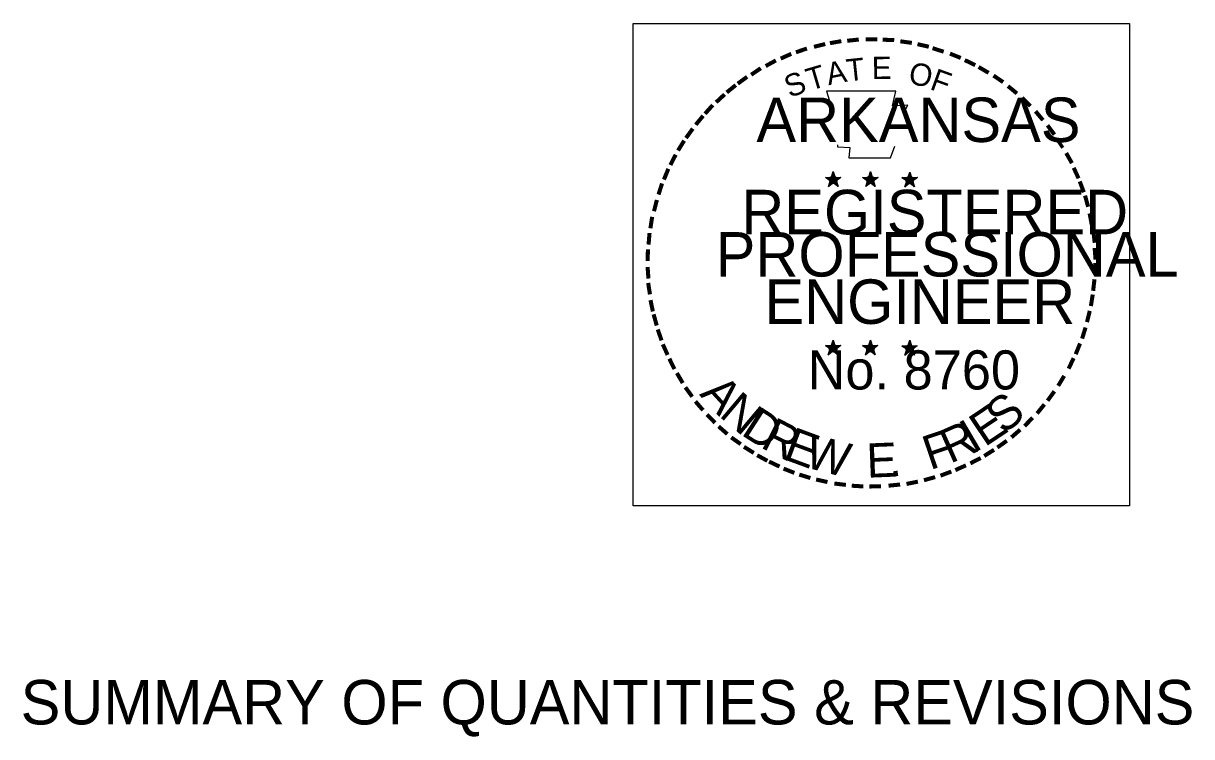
# Model space of a CAD drawing. Extents: x 1226912 to 1228117, y 151309 to 152323.
# Drawn here: x 1227768.2 to 1228096.3, y 151309.4 to 151509.9 of the extents above; entities that cross this region are included whole.
import ezdxf

# ---------------------------------------------------------------- set-up
doc = ezdxf.new("R2010")
doc.units = 0
for name, color, linetype in [('R_Border Notes', 7, 'Continuous'), ('R_Border PE', 7, 'Continuous'), ('R_Border Prem', 7, 'Continuous')]:
    doc.layers.add(name, color=color, linetype=linetype)

msp = doc.modelspace()

# ---------------------------------------------------------------- linework, layer by layer
at = {"layer": 'R_Border PE'}
for p, q in [((1227995.64, 151468.22), (1227995.33, 151466.66)), ((1227995.64, 151468.22), (1227995.39, 151466.6)), ((1227995.64, 151468.22), (1227995.58, 151466.66)), ((1227995.64, 151465.91), (1227995.64, 151468.22)), ((1227995.64, 151468.22), (1227996.08, 151466.6)), ((1227995.64, 151468.22), (1227995.95, 151466.66)), ((1227995.64, 151468.22), (1227995.83, 151466.66)), ((1228006.08, 151468.22), (1228005.77, 151466.66)), ((1228006.08, 151468.22), (1228005.83, 151466.6)), ((1228006.08, 151468.22), (1228005.95, 151466.66)), ((1228006.08, 151465.91), (1228006.08, 151468.22)), ((1228006.08, 151468.22), (1228006.52, 151466.6)), ((1228006.08, 151468.22), (1228006.39, 151466.66)), ((1228006.08, 151468.22), (1228006.2, 151466.66)), ((1228017.14, 151468.1), (1228016.77, 151466.6)), ((1228017.14, 151468.1), (1228016.89, 151466.54)), ((1228017.14, 151468.1), (1228017.02, 151466.54)), ((1228017.14, 151465.85), (1228017.14, 151468.1)), ((1228017.14, 151468.1), (1228017.58, 151466.54)), ((1228017.14, 151468.1), (1228017.45, 151466.54)), ((1228017.14, 151468.1), (1228017.27, 151466.6)), ((1227993.45, 151466.6), (1227995.64, 151465.91)), ((1227993.45, 151466.6), (1227995.08, 151466.47)), ((1227993.45, 151466.6), (1227995.08, 151466.35)), ((1227993.45, 151466.6), (1227995.02, 151466.22)), ((1227993.45, 151466.6), (1227995.02, 151465.97)), ((1227993.45, 151466.6), (1227994.95, 151465.85)), ((1227993.45, 151466.6), (1227994.95, 151465.72)), ((1227994.33, 151464.04), (1227995.64, 151465.91)), ((1227994.33, 151464.04), (1227995.02, 151465.79)), ((1227994.33, 151464.04), (1227995.08, 151465.6)), ((1227994.33, 151464.04), (1227995.2, 151465.54)), ((1227994.33, 151464.04), (1227995.64, 151465.41)), ((1227994.33, 151464.04), (1227995.39, 151465.35)), ((1227994.33, 151464.04), (1227995.7, 151465.22)), ((1227997.83, 151466.6), (1227995.64, 151465.91)), ((1227997.02, 151464.04), (1227995.64, 151465.91)), ((1227997.02, 151464.04), (1227995.64, 151465.41)), ((1227997.02, 151464.04), (1227995.64, 151465.22)), ((1227997.83, 151466.6), (1227995.89, 151466.47)), ((1227997.02, 151464.04), (1227995.89, 151465.35)), ((1227997.83, 151466.6), (1227996.02, 151466.29)), ((1227997.83, 151466.6), (1227996.02, 151466.16)), ((1227997.02, 151464.04), (1227996.08, 151465.6)), ((1227997.02, 151464.04), (1227996.14, 151465.85)), ((1227997.02, 151464.04), (1227996.27, 151465.91)), ((1227997.83, 151466.6), (1227996.45, 151466.04)), ((1227997.83, 151466.6), (1227996.58, 151465.97)), ((1227997.83, 151466.6), (1227996.64, 151465.91)), ((1228003.89, 151466.6), (1228006.08, 151465.91)), ((1228003.89, 151466.6), (1228005.52, 151466.47)), ((1228003.89, 151466.6), (1228005.52, 151466.35)), ((1228003.89, 151466.6), (1228005.45, 151466.22)), ((1228003.89, 151466.6), (1228005.39, 151465.97)), ((1228003.89, 151466.6), (1228005.39, 151465.85)), ((1228003.89, 151466.6), (1228005.39, 151465.72)), ((1228004.77, 151464.04), (1228006.08, 151465.91)), ((1228004.77, 151464.04), (1228005.45, 151465.79)), ((1228004.77, 151464.04), (1228005.52, 151465.6)), ((1228004.77, 151464.04), (1228005.64, 151465.54)), ((1228004.77, 151464.04), (1228006.08, 151465.41)), ((1228004.77, 151464.04), (1228005.83, 151465.35)), ((1228004.77, 151464.04), (1228006.14, 151465.22)), ((1228008.27, 151466.6), (1228006.08, 151465.91)), ((1228007.45, 151464.04), (1228006.08, 151465.91)), ((1228007.45, 151464.04), (1228006.08, 151465.41)), ((1228007.45, 151464.04), (1228006.08, 151465.22)), ((1228008.27, 151466.6), (1228006.33, 151466.47)), ((1228007.45, 151464.04), (1228006.33, 151465.35)), ((1228008.27, 151466.6), (1228006.45, 151466.29)), ((1228008.27, 151466.6), (1228006.45, 151466.16)), ((1228007.45, 151464.04), (1228006.52, 151465.6)), ((1228007.45, 151464.04), (1228006.58, 151465.85)), ((1228007.45, 151464.04), (1228006.7, 151465.91)), ((1228008.27, 151466.6), (1228006.89, 151466.04)), ((1228008.27, 151466.6), (1228007.02, 151465.97)), ((1228008.27, 151466.6), (1228007.08, 151465.91)), ((1228014.95, 151466.54), (1228017.14, 151465.85)), ((1228014.95, 151466.54), (1228016.58, 151466.35)), ((1228014.95, 151466.54), (1228016.52, 151466.22)), ((1228014.95, 151466.54), (1228016.52, 151466.16)), ((1228014.95, 151466.54), (1228016.45, 151465.91)), ((1228014.95, 151466.54), (1228016.45, 151465.79)), ((1228014.95, 151466.54), (1228016.45, 151465.66)), ((1228015.77, 151463.97), (1228017.14, 151465.85)), ((1228015.77, 151463.97), (1228016.52, 151465.72)), ((1228015.77, 151463.97), (1228016.58, 151465.54)), ((1228015.77, 151463.97), (1228016.7, 151465.47)), ((1228015.77, 151463.97), (1228017.14, 151465.35)), ((1228015.77, 151463.97), (1228016.89, 151465.29)), ((1228015.77, 151463.97), (1228017.2, 151465.16)), ((1228019.33, 151466.54), (1228017.14, 151465.85)), ((1228018.45, 151463.97), (1228017.14, 151465.85)), ((1228018.45, 151463.97), (1228017.14, 151465.35)), ((1228018.45, 151463.97), (1228017.14, 151465.16)), ((1228019.33, 151466.54), (1228017.39, 151466.41)), ((1228018.45, 151463.97), (1228017.39, 151465.29)), ((1228019.33, 151466.54), (1228017.52, 151466.22)), ((1228019.33, 151466.54), (1228017.52, 151466.1)), ((1228018.45, 151463.97), (1228017.58, 151465.54)), ((1228018.45, 151463.97), (1228017.64, 151465.79)), ((1228018.45, 151463.97), (1228017.77, 151465.79)), ((1228019.33, 151466.54), (1228017.95, 151465.97)), ((1228019.33, 151466.54), (1228018.02, 151465.91)), ((1228019.33, 151466.54), (1228018.14, 151465.85)), ((1227993.45, 151419.29), (1227995.64, 151418.6)), ((1227993.45, 151419.29), (1227995.08, 151419.1)), ((1227993.45, 151419.29), (1227995.02, 151418.97)), ((1227993.45, 151419.29), (1227995.02, 151418.91)), ((1227993.45, 151419.29), (1227994.95, 151418.66)), ((1227993.45, 151419.29), (1227994.95, 151418.54)), ((1227993.45, 151419.29), (1227994.95, 151418.41)), ((1227994.27, 151416.72), (1227995.64, 151418.6)), ((1227994.27, 151416.72), (1227995.02, 151418.47)), ((1227995.64, 151420.85), (1227995.27, 151419.35)), ((1227995.64, 151420.85), (1227995.39, 151419.29)), ((1227995.64, 151420.85), (1227995.52, 151419.29)), ((1227995.64, 151418.6), (1227995.64, 151420.85)), ((1227995.64, 151420.85), (1227996.08, 151419.29)), ((1227995.64, 151420.85), (1227995.95, 151419.29)), ((1227995.64, 151420.85), (1227995.77, 151419.29)), ((1227997.83, 151419.29), (1227995.64, 151418.6)), ((1227996.95, 151416.72), (1227995.64, 151418.6)), ((1227997.83, 151419.29), (1227995.89, 151419.16)), ((1227997.83, 151419.29), (1227996.02, 151418.97)), ((1227997.83, 151419.29), (1227996.02, 151418.85)), ((1227996.95, 151416.72), (1227996.08, 151418.54)), ((1227996.95, 151416.72), (1227996.08, 151418.29)), ((1227996.95, 151416.72), (1227996.27, 151418.54)), ((1227997.83, 151419.29), (1227996.39, 151418.72)), ((1227997.83, 151419.29), (1227996.52, 151418.66)), ((1227997.83, 151419.29), (1227996.64, 151418.54)), ((1228003.89, 151419.29), (1228006.08, 151418.6)), ((1228003.89, 151419.29), (1228005.45, 151419.1)), ((1228003.89, 151419.29), (1228005.45, 151418.97)), ((1228003.89, 151419.29), (1228005.45, 151418.91)), ((1228003.89, 151419.29), (1228005.39, 151418.66)), ((1228003.89, 151419.29), (1228005.39, 151418.54)), ((1228003.89, 151419.29), (1228005.39, 151418.41)), ((1228004.7, 151416.72), (1228006.08, 151418.6)), ((1228004.7, 151416.72), (1228005.45, 151418.47)), ((1228006.08, 151420.85), (1228005.7, 151419.35)), ((1228006.08, 151420.85), (1228005.83, 151419.29)), ((1228006.08, 151420.85), (1228005.95, 151419.29)), ((1228006.08, 151418.6), (1228006.08, 151420.85)), ((1228006.08, 151420.85), (1228006.45, 151419.29)), ((1228006.08, 151420.85), (1228006.39, 151419.29)), ((1228006.08, 151420.85), (1228006.2, 151419.29)), ((1228008.2, 151419.29), (1228006.08, 151418.6)), ((1228007.39, 151416.72), (1228006.08, 151418.6)), ((1228008.2, 151419.29), (1228006.33, 151419.16)), ((1228008.2, 151419.29), (1228006.45, 151418.97)), ((1228008.2, 151419.29), (1228006.45, 151418.85)), ((1228007.39, 151416.72), (1228006.52, 151418.54)), ((1228007.39, 151416.72), (1228006.52, 151418.29)), ((1228007.39, 151416.72), (1228006.7, 151418.54)), ((1228008.2, 151419.29), (1228006.83, 151418.72)), ((1228008.2, 151419.29), (1228006.95, 151418.66)), ((1228008.2, 151419.29), (1228007.08, 151418.54)), ((1228014.95, 151419.22), (1228017.14, 151418.54)), ((1228014.95, 151419.22), (1228016.52, 151419.04)), ((1228014.95, 151419.22), (1228016.52, 151418.91)), ((1228014.95, 151419.22), (1228016.45, 151418.79)), ((1228014.95, 151419.22), (1228016.45, 151418.6)), ((1228014.95, 151419.22), (1228016.39, 151418.41)), ((1228014.95, 151419.22), (1228016.39, 151418.29)), ((1228015.77, 151416.66), (1228017.14, 151418.54)), ((1228015.77, 151416.66), (1228016.45, 151418.41)), ((1228017.14, 151420.79), (1228016.77, 151419.22)), ((1228017.14, 151420.79), (1228016.89, 151419.22)), ((1228017.14, 151420.79), (1228017.02, 151419.22)), ((1228017.14, 151418.54), (1228017.14, 151420.79)), ((1228017.14, 151420.79), (1228017.52, 151419.22)), ((1228017.14, 151420.79), (1228017.45, 151419.22)), ((1228017.14, 151420.79), (1228017.27, 151419.22)), ((1228019.27, 151419.22), (1228017.14, 151418.54)), ((1228018.45, 151416.66), (1228017.14, 151418.54)), ((1228019.27, 151419.22), (1228017.39, 151419.1)), ((1228019.27, 151419.22), (1228017.52, 151418.91)), ((1228019.27, 151419.22), (1228017.52, 151418.79)), ((1228018.45, 151416.66), (1228017.58, 151418.47)), ((1228018.45, 151416.66), (1228017.7, 151418.47)), ((1228019.27, 151419.22), (1228017.89, 151418.66)), ((1228019.27, 151419.22), (1228018.02, 151418.54)), ((1228019.27, 151419.22), (1228018.08, 151418.47)), ((1227994.27, 151416.72), (1227995.08, 151418.22)), ((1227994.27, 151416.72), (1227995.2, 151418.16)), ((1227994.27, 151416.72), (1227995.64, 151418.1)), ((1227994.27, 151416.72), (1227995.39, 151418.04)), ((1227994.27, 151416.72), (1227995.64, 151417.91)), ((1227996.95, 151416.72), (1227995.58, 151417.91)), ((1227996.95, 151416.72), (1227995.64, 151418.04)), ((1227996.95, 151416.72), (1227995.83, 151418.04)), ((1228004.7, 151416.72), (1228005.52, 151418.22)), ((1228004.7, 151416.72), (1228005.64, 151418.16)), ((1228004.7, 151416.72), (1228006.08, 151418.1)), ((1228004.7, 151416.72), (1228005.83, 151418.04)), ((1228004.7, 151416.72), (1228006.08, 151417.91)), ((1228007.39, 151416.72), (1228006.02, 151417.91)), ((1228007.39, 151416.72), (1228006.08, 151418.04)), ((1228007.39, 151416.72), (1228006.27, 151418.04)), ((1228015.77, 151416.66), (1228016.52, 151418.16)), ((1228015.77, 151416.66), (1228016.7, 151418.1)), ((1228015.77, 151416.66), (1228016.89, 151417.97)), ((1228015.77, 151416.66), (1228017.08, 151417.97)), ((1228015.77, 151416.66), (1228017.14, 151417.85)), ((1228018.45, 151416.66), (1228017.08, 151417.97)), ((1228018.45, 151416.66), (1228017.08, 151417.79)), ((1228018.45, 151416.66), (1228017.33, 151417.97)), ((1228018.45, 151416.66), (1228017.52, 151418.16))]:
    msp.add_line(p, q, dxfattribs=at)
for points in [[(1227993.77, 151490.85), (1227995.39, 151485.66)], [(1228015.7, 151485.1), (1228016.58, 151486.85), (1228012.27, 151486.72), (1228013.2, 151490.85), (1227993.77, 151490.85)], [(1227996.83, 151475.72), (1227996.83, 151475.16), (1228000.33, 151475.04), (1228000.02, 151472.1), (1228011.7, 151472.1), (1228012.95, 151475.41)], [(1227995.64, 151468.22), (1227997.02, 151464.04), (1227993.45, 151466.6), (1227997.83, 151466.6), (1227994.33, 151464.04), (1227995.64, 151468.22)], [(1228006.08, 151468.22), (1228007.45, 151464.04), (1228003.89, 151466.6), (1228008.27, 151466.6), (1228004.77, 151464.04), (1228006.08, 151468.22)], [(1228017.14, 151468.1), (1228018.45, 151463.97), (1228014.95, 151466.54), (1228019.33, 151466.54), (1228015.77, 151463.97), (1228017.14, 151468.1)], [(1227995.64, 151420.85), (1227996.95, 151416.72), (1227993.45, 151419.29), (1227997.83, 151419.29), (1227994.27, 151416.72), (1227995.64, 151420.85)], [(1228006.08, 151420.85), (1228007.39, 151416.72), (1228003.89, 151419.29), (1228008.2, 151419.29), (1228004.7, 151416.72), (1228006.08, 151420.85)], [(1228017.14, 151420.79), (1228018.45, 151416.66), (1228014.95, 151419.22), (1228019.27, 151419.22), (1228015.77, 151416.66), (1228017.14, 151420.79)]]:
    msp.add_lwpolyline(points, dxfattribs=at)
for centre, radius in [((1227995.66, 151465.91), 1.08), ((1227995.66, 151465.91), 0.975), ((1227995.66, 151465.91), 0.904), ((1227995.66, 151465.91), 0.83), ((1227995.66, 151465.91), 0.723), ((1227995.66, 151465.91), 0.672), ((1227995.66, 151465.91), 0.619), ((1227995.66, 151465.91), 0.533), ((1227995.66, 151465.91), 0.467), ((1227995.66, 151465.91), 0.388), ((1227995.66, 151465.91), 0.31), ((1227995.66, 151465.91), 0.231), ((1227995.66, 151465.91), 0.185), ((1227995.66, 151465.91), 0.0901), ((1228006.09, 151465.91), 1.08), ((1228006.09, 151465.91), 0.975), ((1228006.09, 151465.91), 0.904), ((1228006.09, 151465.91), 0.83), ((1228006.09, 151465.91), 0.723), ((1228006.09, 151465.91), 0.672), ((1228006.09, 151465.91), 0.619), ((1228006.09, 151465.91), 0.533), ((1228006.09, 151465.91), 0.467), ((1228006.09, 151465.91), 0.388), ((1228006.09, 151465.91), 0.31), ((1228006.09, 151465.91), 0.231), ((1228006.09, 151465.91), 0.185), ((1228006.09, 151465.91), 0.0901), ((1228017.14, 151465.83), 1.08), ((1228017.14, 151465.83), 0.975), ((1228017.14, 151465.83), 0.904), ((1228017.14, 151465.83), 0.83), ((1228017.14, 151465.83), 0.723), ((1228017.14, 151465.83), 0.672), ((1228017.14, 151465.83), 0.619), ((1228017.14, 151465.83), 0.533), ((1228017.14, 151465.83), 0.467), ((1228017.14, 151465.83), 0.388), ((1228017.14, 151465.83), 0.31), ((1228017.14, 151465.83), 0.231), ((1228017.14, 151465.83), 0.185), ((1228017.14, 151465.83), 0.0901), ((1227995.63, 151418.57), 1.08), ((1227995.63, 151418.57), 0.975), ((1227995.63, 151418.57), 0.904), ((1227995.63, 151418.57), 0.83), ((1227995.63, 151418.57), 0.723), ((1227995.63, 151418.57), 0.672), ((1227995.63, 151418.57), 0.619), ((1227995.63, 151418.57), 0.533), ((1227995.63, 151418.57), 0.467), ((1227995.63, 151418.57), 0.388), ((1227995.63, 151418.57), 0.31), ((1227995.63, 151418.57), 0.231), ((1227995.63, 151418.57), 0.185), ((1227995.63, 151418.57), 0.0901), ((1228006.07, 151418.57), 1.08), ((1228006.07, 151418.57), 0.975), ((1228006.07, 151418.57), 0.904), ((1228006.07, 151418.57), 0.83), ((1228006.07, 151418.57), 0.723), ((1228006.07, 151418.57), 0.672), ((1228006.07, 151418.57), 0.619), ((1228006.07, 151418.57), 0.533), ((1228006.07, 151418.57), 0.467), ((1228006.07, 151418.57), 0.388), ((1228006.07, 151418.57), 0.31), ((1228006.07, 151418.57), 0.231), ((1228006.07, 151418.57), 0.185), ((1228006.07, 151418.57), 0.0901), ((1228017.11, 151418.5), 1.08), ((1228017.11, 151418.5), 0.975), ((1228017.11, 151418.5), 0.904), ((1228017.11, 151418.5), 0.83), ((1228017.11, 151418.5), 0.723), ((1228017.11, 151418.5), 0.672), ((1228017.11, 151418.5), 0.619), ((1228017.11, 151418.5), 0.533), ((1228017.11, 151418.5), 0.467), ((1228017.11, 151418.5), 0.388), ((1228017.11, 151418.5), 0.31), ((1228017.11, 151418.5), 0.231), ((1228017.11, 151418.5), 0.185), ((1228017.11, 151418.5), 0.0901)]:
    msp.add_circle(centre, radius, dxfattribs=at)
at = {"layer": 'R_Border Prem'}
msp.add_lwpolyline([(1227939.42, 151509.89), (1228078.92, 151509.89), (1228078.92, 151374.27), (1227939.42, 151374.27)], close=True, dxfattribs=at)

# ---------------------------------------------------------------- texts
at = {"layer": 'R_Border Notes'}
msp.add_text('SUMMARY OF QUANTITIES & REVISIONS', height=12.5, dxfattribs=at).set_placement((1227767.4, 151312.82))
at = {"layer": 'R_Border PE'}
for s, height, rotation, p in [('-', 10, 13.6302, (1227990.58, 151499.41)), ('-', 10, 10.2193, (1227994.83, 151500.41)), ('-', 10, 5.8968, (1227999.39, 151501.1)), ('-', 10, 0.1862, (1228004.2, 151501.54)), ('-', 10, 357.743, (1228008.77, 151501.47)), ('-', 10, 352.1617, (1228013.39, 151501.1)), ('-', 10, 347.2049, (1228017.89, 151500.41)), ('-', 10, 24.3072, (1227981.95, 151496.22)), ('-', 10, 19.1761, (1227985.89, 151497.91)), ('E', 6.25, 0.8323, (1228006.52, 151494.22)), ('-', 10, 342.3362, (1228021.83, 151499.41)), ('-', 10, 337.8551, (1228026.45, 151498.04)), ('-', 10, 34.0636, (1227974.27, 151491.91)), ('-', 10, 28.7918, (1227978.02, 151494.22)), ('T', 6.25, 16.4036, (1227989.14, 151490.91)), ('A', 6.25, 11.2132, (1227994.33, 151492.47)), ('T', 6.25, 6.0228, (1227999.64, 151493.54)), ('O', 6.25, 350.4515, (1228016.58, 151492.91)), ('F', 6.25, 340.0707, (1228022.52, 151491.47)), ('-', 10, 334.1211, (1228030.39, 151496.35)), ('-', 10, 329.6409, (1228034.02, 151494.6)), ('-', 10, 36.2317, (1227970.64, 151489.47)), ('S', 6.25, 21.594, (1227983.45, 151488.85)), ('-', 10, 325.8627, (1228038.02, 151492.35)), ('-', 10, 38.9507, (1227967.7, 151487.1)), ('-', 10, 320.5297, (1228041.83, 151489.66)), ('-', 10, 48.423, (1227962.14, 151481.47)), ('-', 10, 42.9622, (1227964.95, 151484.47)), ('-', 10, 315.5786, (1228045.58, 151486.6)), ('-', 10, 50.6142, (1227959.64, 151478.47)), ('-', 10, 309.8797, (1228049.14, 151483.16)), ('-', 10, 306.6522, (1228052.39, 151479.41)), ('-', 10, 54.2325, (1227957.08, 151474.91)), ('-', 8.75, 303.6753, (1228055.45, 151475.85)), ('-', 10, 58.0706, (1227955.02, 151471.6)), ('-', 10, 62.8713, (1227953.08, 151467.79)), ('-', 10, 299.6684, (1228057.45, 151472.04)), ('-', 10, 67.7743, (1227951.45, 151463.97)), ('-', 10, 294.6628, (1228059.45, 151468.22)), ('-', 10, 72.3945, (1227950.08, 151460.04)), ('-', 10, 290.5728, (1228061.08, 151464.66)), ('-', 10, 285.1233, (1228062.52, 151461.04)), ('-', 10, 75.461, (1227948.89, 151455.54)), ('-', 10, 81.2013, (1227948.02, 151451.1)), ('-', 10, 280.5493, (1228063.77, 151456.35)), ('-', 10, 276.5962, (1228064.83, 151451.6)), ('-', 10, 85.1863, (1227947.58, 151446.79)), ('-', 10, 89.0622, (1227947.39, 151442.41)), ('-', 10, 274.3301, (1228065.2, 151447.04)), ('-', 10, 94.1959, (1227947.64, 151437.85)), ('-', 10, 269.9407, (1228065.39, 151443.1)), ('-', 10, 263.5172, (1228065.27, 151438.97)), ('-', 10, 98.9479, (1227948.08, 151433.72)), ('-', 10, 101.7149, (1227948.89, 151429.1)), ('-', 10, 260.9953, (1228064.83, 151434.85)), ('-', 10, 105.4578, (1227949.95, 151425.41)), ('-', 10, 255.7626, (1228064.14, 151430.6)), ('-', 10, 109.0874, (1227951.27, 151421.47)), ('-', 10, 252.8681, (1228063.02, 151426.1)), ('-', 10, 114.0643, (1227952.89, 151417.72)), ('-', 10, 247.8887, (1228061.64, 151421.91)), ('-', 10, 115.7289, (1227954.77, 151413.85)), ('-', 10, 244.6197, (1228059.95, 151417.97)), ('-', 10, 120.4471, (1227957.02, 151410.22)), ('A', 9.62, 312.4727, (1227957.89, 151405.53)), ('-', 10, 239.0712, (1228057.52, 151413.29)), ('-', 10, 125.8934, (1227959.52, 151406.72)), ('N', 9.62, 319.8362, (1227963.32, 151399.6)), ('S', 9.62, 39.723, (1228043.56, 151394.13)), ('-', 10, 233.8452, (1228055.02, 151409.22)), ('-', 10, 130.7181, (1227962.39, 151403.22)), ('D', 9.62, 327.1996, (1227969.47, 151394.41)), ('E', 9.62, 33.8878, (1228038.22, 151390.65)), ('-', 10, 231.2538, (1228052.33, 151405.66)), ('-', 10, 134.2238, (1227965.64, 151399.85)), ('R', 9.62, 333.1738, (1227974.91, 151390.81)), ('-', 10, 225.7653, (1228049.33, 151402.16)), ('-', 10, 138.9338, (1227968.89, 151396.97)), ('E', 9.62, 339.7037, (1227981.26, 151387.54)), ('F', 9.62, 18.6051, (1228022.84, 151384.25)), ('R', 9.62, 24.0235, (1228028.48, 151386.05)), ('I', 9.62, 30.5534, (1228035.02, 151388.91)), ('-', 10, 221.0851, (1228046.08, 151398.97)), ('-', 10, 144.6463, (1227972.39, 151394.41)), ('W', 9.62, 345.5389, (1227987.21, 151385.25)), ('E', 9.62, 2.2804, (1228005.18, 151382.16)), ('-', 10, 215.7363, (1228042.64, 151396.04)), ('-', 10, 148.0898, (1227975.89, 151392.1)), ('-', 10, 151.5704, (1227979.52, 151390.04)), ('-', 10, 212.2491, (1228039.27, 151393.6)), ('-', 10, 154.6002, (1227982.77, 151388.54)), ('-', 10, 204.2516, (1228031.89, 151389.41)), ('-', 10, 207.3568, (1228035.83, 151391.41)), ('-', 10, 158.5612, (1227986.7, 151386.91)), ('-', 10, 162.7983, (1227990.95, 151385.6)), ('-', 10, 167.5555, (1227995.45, 151384.6)), ('.', 9.62, 8.1156, (1228011.55, 151382.33)), ('-', 10, 195.4743, (1228023.83, 151386.22)), ('-', 10, 200.7184, (1228028.02, 151387.72)), ('-', 10, 173.1155, (1228000.27, 151383.91)), ('-', 10, 176.5183, (1228004.95, 151383.54)), ('-', 10, 181.5918, (1228009.58, 151383.66)), ('-', 10, 185.8167, (1228014.64, 151384.16)), ('-', 10, 191.2858, (1228019.27, 151384.97))]:
    msp.add_text(s, height=height, rotation=rotation, dxfattribs=at).set_placement(p)
for s, height, p in [('ARKANSAS', 12.5, (1227974.08, 151476.54)), ('REGISTERED', 12.5, (1227969.83, 151450.6)), ('PROFESSIONAL', 12.4999, (1227962.64, 151438.72)), ('ENGINEER', 12.5, (1227976.33, 151425.41)), ('No. 8760', 11, (1227988.44, 151406.97))]:
    msp.add_text(s, height=height, dxfattribs=at).set_placement(p)

doc.saveas('drawing.dxf')
